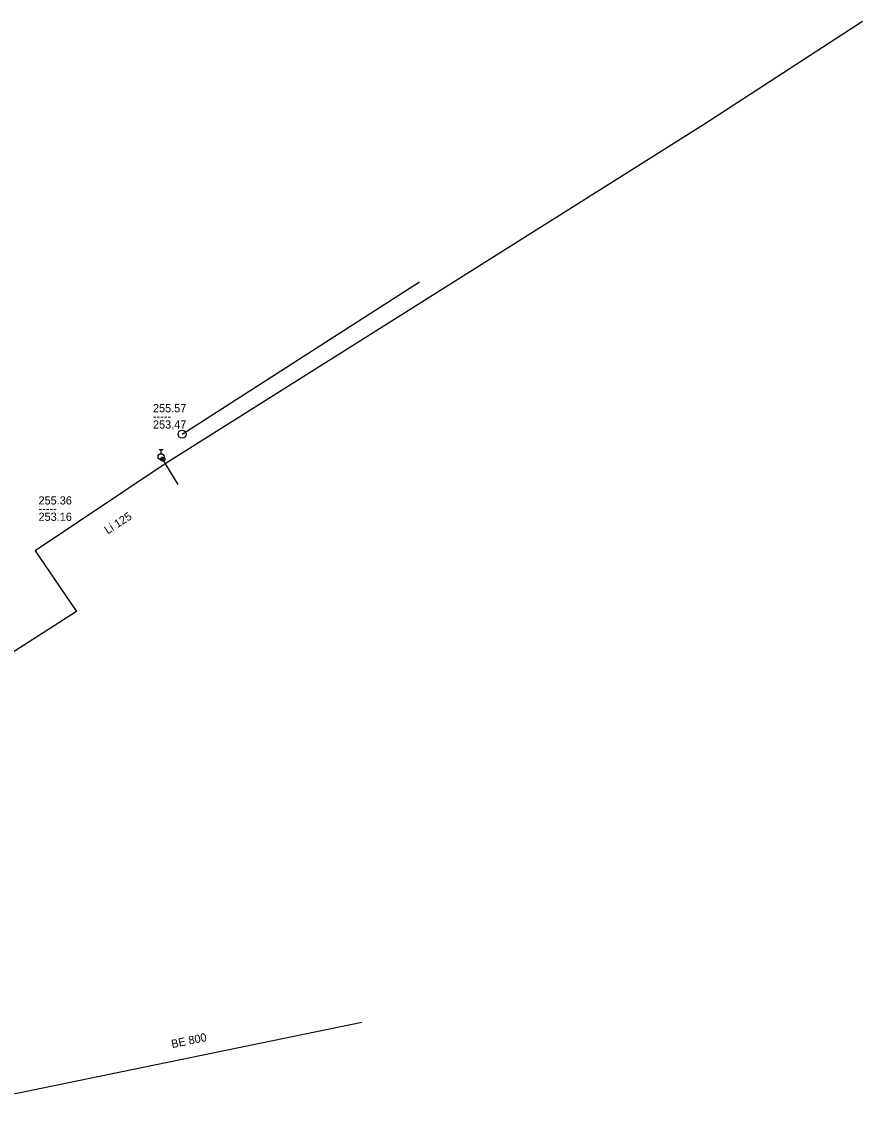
# Model space of a CAD drawing. Extents: x -647357 to -646700, y -1072205 to -1071664.
# Drawn here: x -646802.6 to -646699.6, y -1072139 to -1072006.6 of the extents above; entities that cross this region are included whole.
import ezdxf

# ---------------------------------------------------------------- set-up
doc = ezdxf.new("R2010")
doc.units = 0
for name, color, linetype in [('Level 19', 7, 'Continuous'), ('Level 20', 7, 'Continuous'), ('Level 21', 7, 'Continuous'), ('Level 24', 7, 'Continuous'), ('Level 26', 7, 'Continuous'), ('Level 40', 7, 'Continuous'), ('Level 41', 7, 'Continuous'), ('Level 44', 7, 'Continuous')]:
    doc.layers.add(name, color=color, linetype=linetype)

msp = doc.modelspace()

# ---------------------------------------------------------------- linework, layer by layer
at = {"layer": 'Level 19'}
msp.add_line((-646784.97, -1072060.71), (-646783.45, -1072063.23), dxfattribs=at)
at = {"layer": 'Level 20'}
for p, q in [((-646699.58, -1072006.57), (-646718.92, -1072019.12)), ((-646718.92, -1072019.12), (-646784.97, -1072060.71)), ((-646785.48, -1072059.83), (-646785.27, -1072060.13)), ((-646784.97, -1072060.71), (-646800.9, -1072071.34)), ((-646785.27, -1072060.13), (-646784.97, -1072060.71)), ((-646800.9, -1072071.34), (-646795.86, -1072078.77)), ((-646795.86, -1072078.77), (-646814.55, -1072090.76))]:
    msp.add_line(p, q, dxfattribs=at)
at = {"layer": 'Level 21'}
for p, q in [((-646785.73, -1072058.955), (-646785.23, -1072058.955)), ((-646785.48, -1072059.455), (-646785.48, -1072058.955))]:
    msp.add_line(p, q, dxfattribs=at)
msp.add_circle((-646785.48, -1072059.83), 0.375, dxfattribs=at)
at = {"layer": 'Level 26'}
msp.add_circle((-646785.27, -1072060.13), 0.25, dxfattribs=at)
at = {"layer": 'Level 40'}
for p, q in [((-646782.91, -1072057.06), (-646753.84, -1072038.42)), ((-646809.3, -1072138.97), (-646760.91, -1072129.04))]:
    msp.add_line(p, q, dxfattribs=at)
at = {"layer": 'Level 41'}
msp.add_circle((-646782.91, -1072057.06), 0.5, dxfattribs=at)

# ---------------------------------------------------------------- texts
at = {"layer": 'Level 24'}
msp.add_text('Li 125', height=1, rotation=32.681, dxfattribs=at).set_placement((-646792.03, -1072069.34))
at = {"layer": 'Level 44'}
for s, p in [('255.57', (-646786.48, -1072054.38)), ('-----', (-646786.48, -1072055.38)), ('253.47', (-646786.48, -1072056.38)), ('255.36', (-646800.5, -1072065.67)), ('-----', (-646800.5, -1072066.67)), ('253.16', (-646800.5, -1072067.67))]:
    msp.add_text(s, height=1, dxfattribs=at).set_placement(p)
msp.add_text('BE 800', height=1, rotation=11.597, dxfattribs=at).set_placement((-646784.13, -1072132.21))

doc.saveas('drawing.dxf')
